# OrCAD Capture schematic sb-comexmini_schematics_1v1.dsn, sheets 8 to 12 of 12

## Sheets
8 POWER: size Custom; title: POWER; note: 8005536002
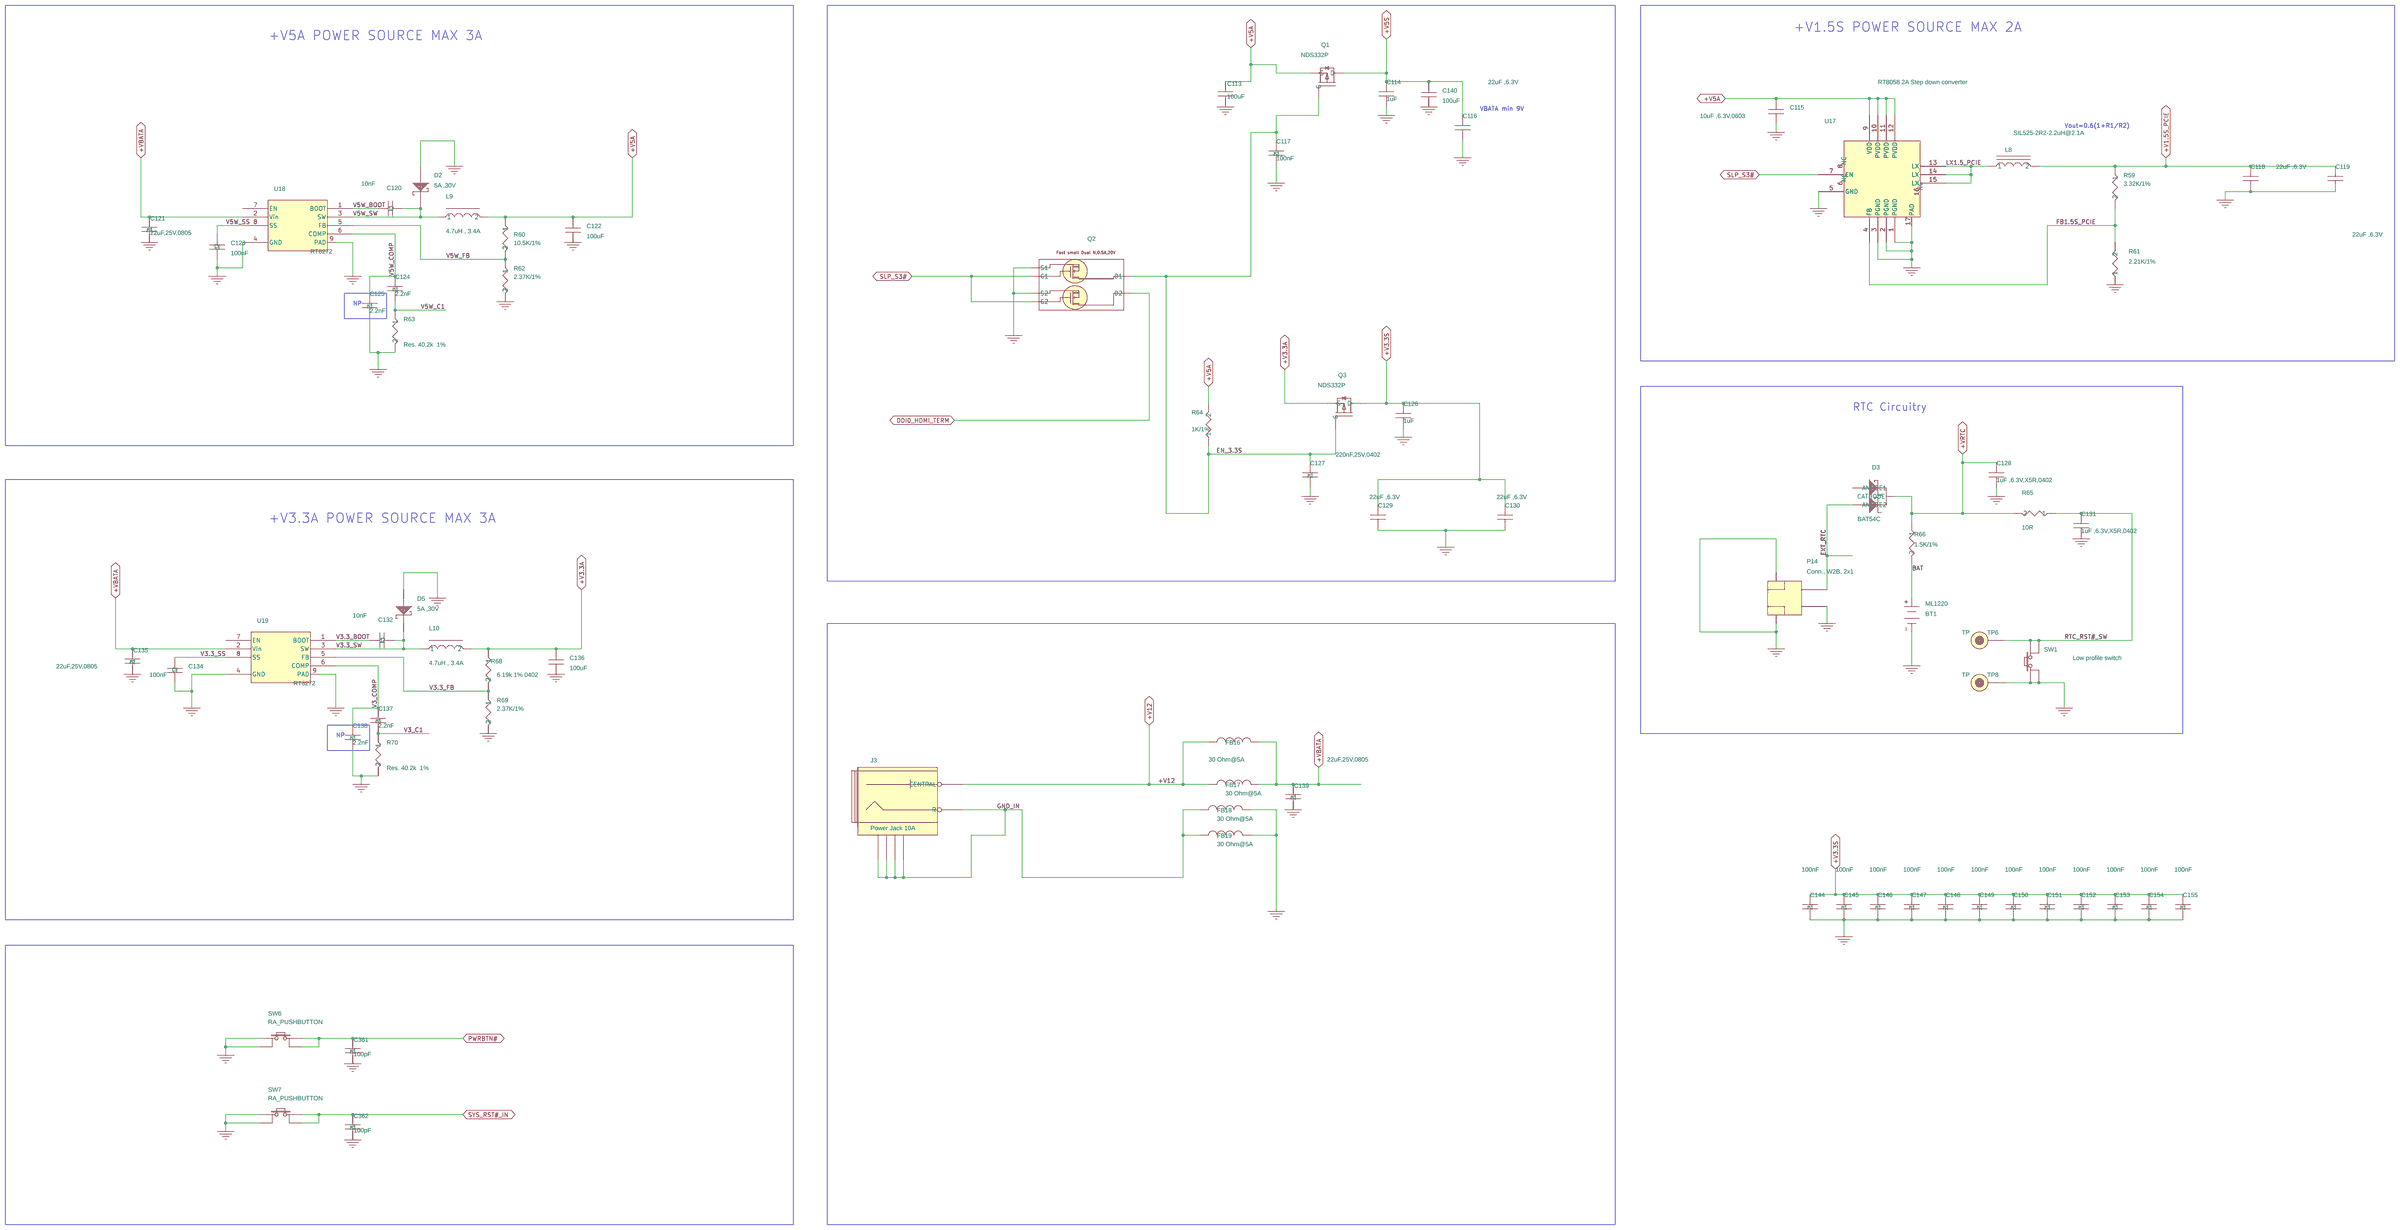
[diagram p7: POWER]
9 SPI BIOS & EC: size Custom; title: DEBUG; note: 8001015000
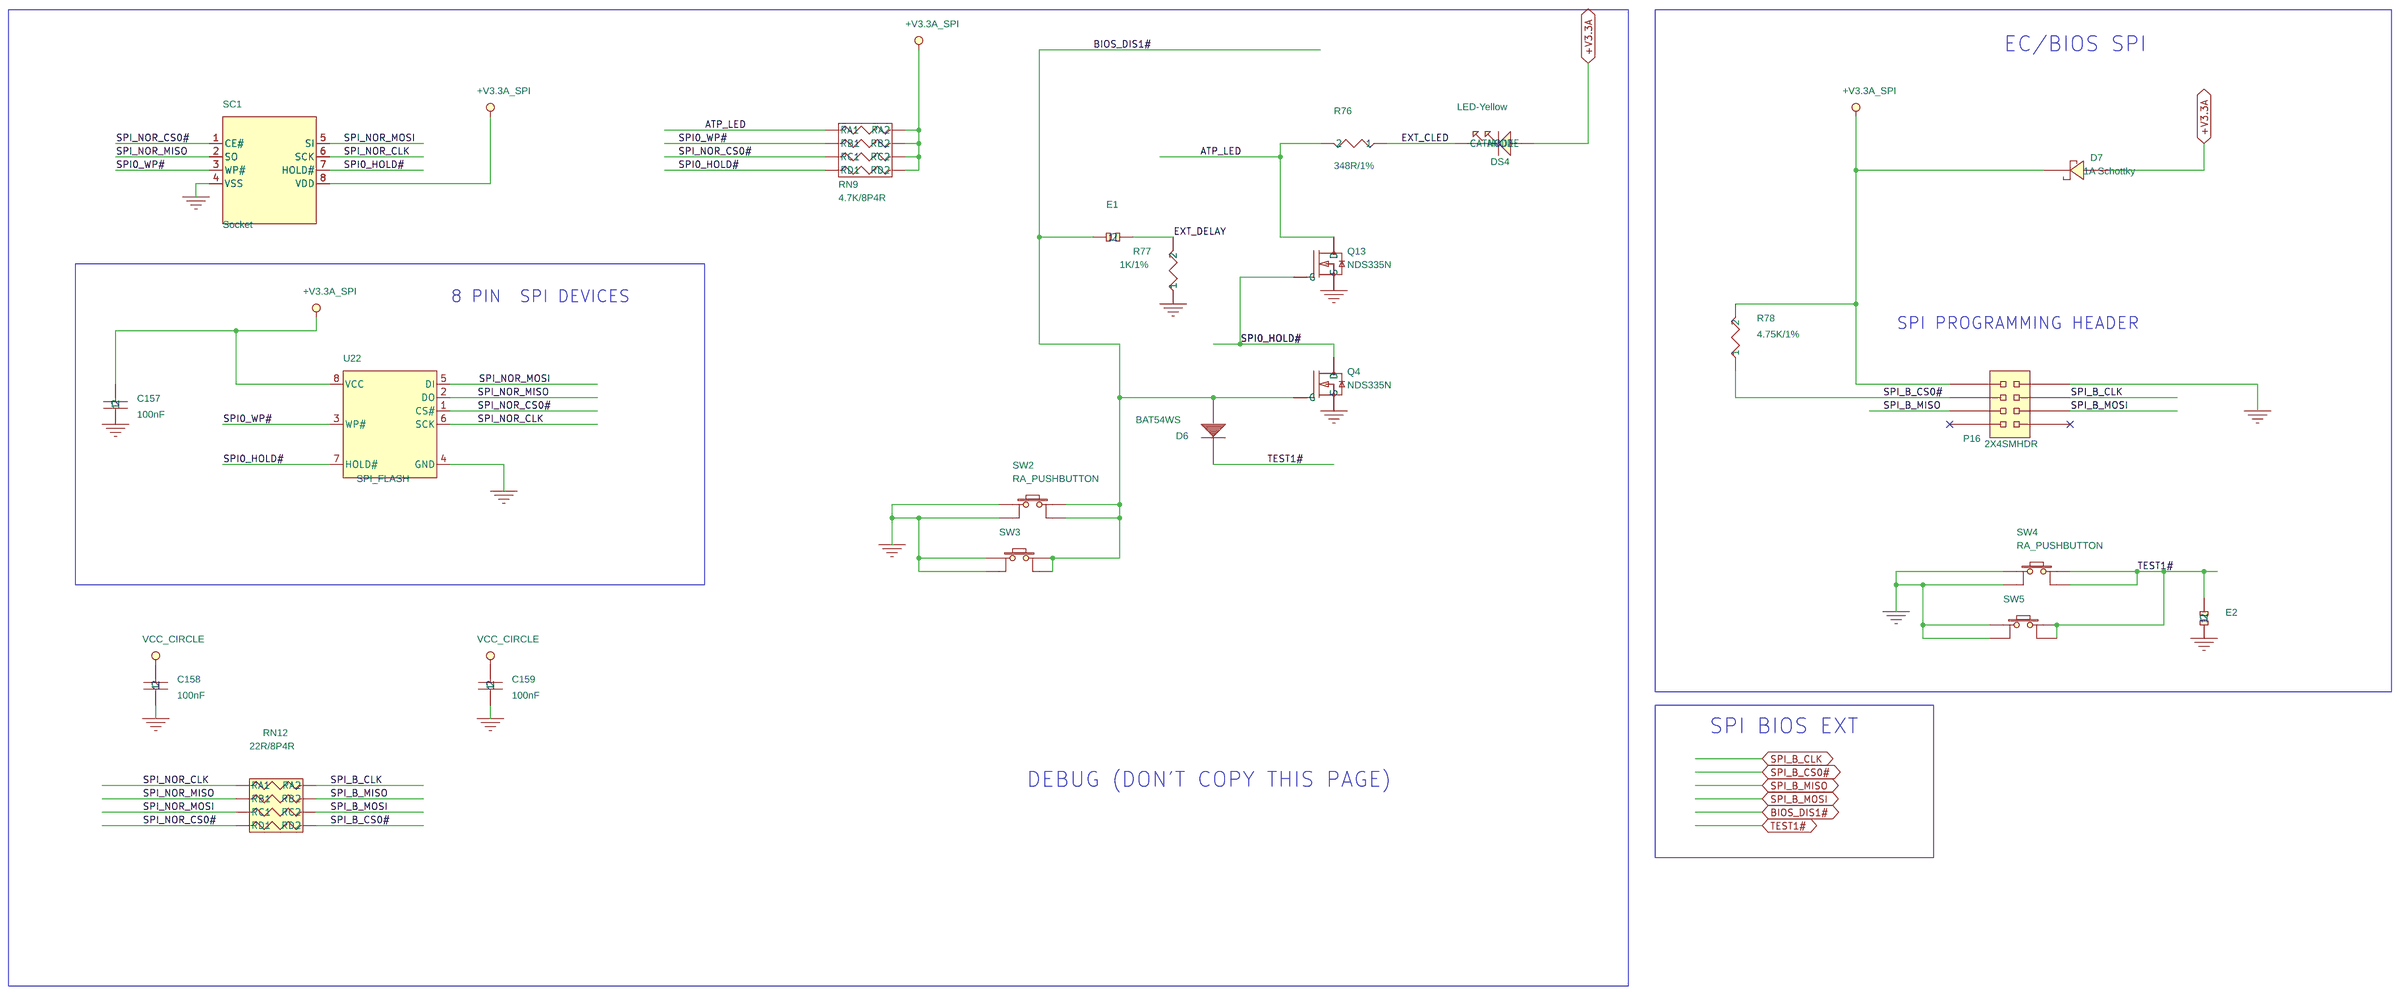
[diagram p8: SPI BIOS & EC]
10 PORT80: size Custom; title: PORT 80; note: 8001015000
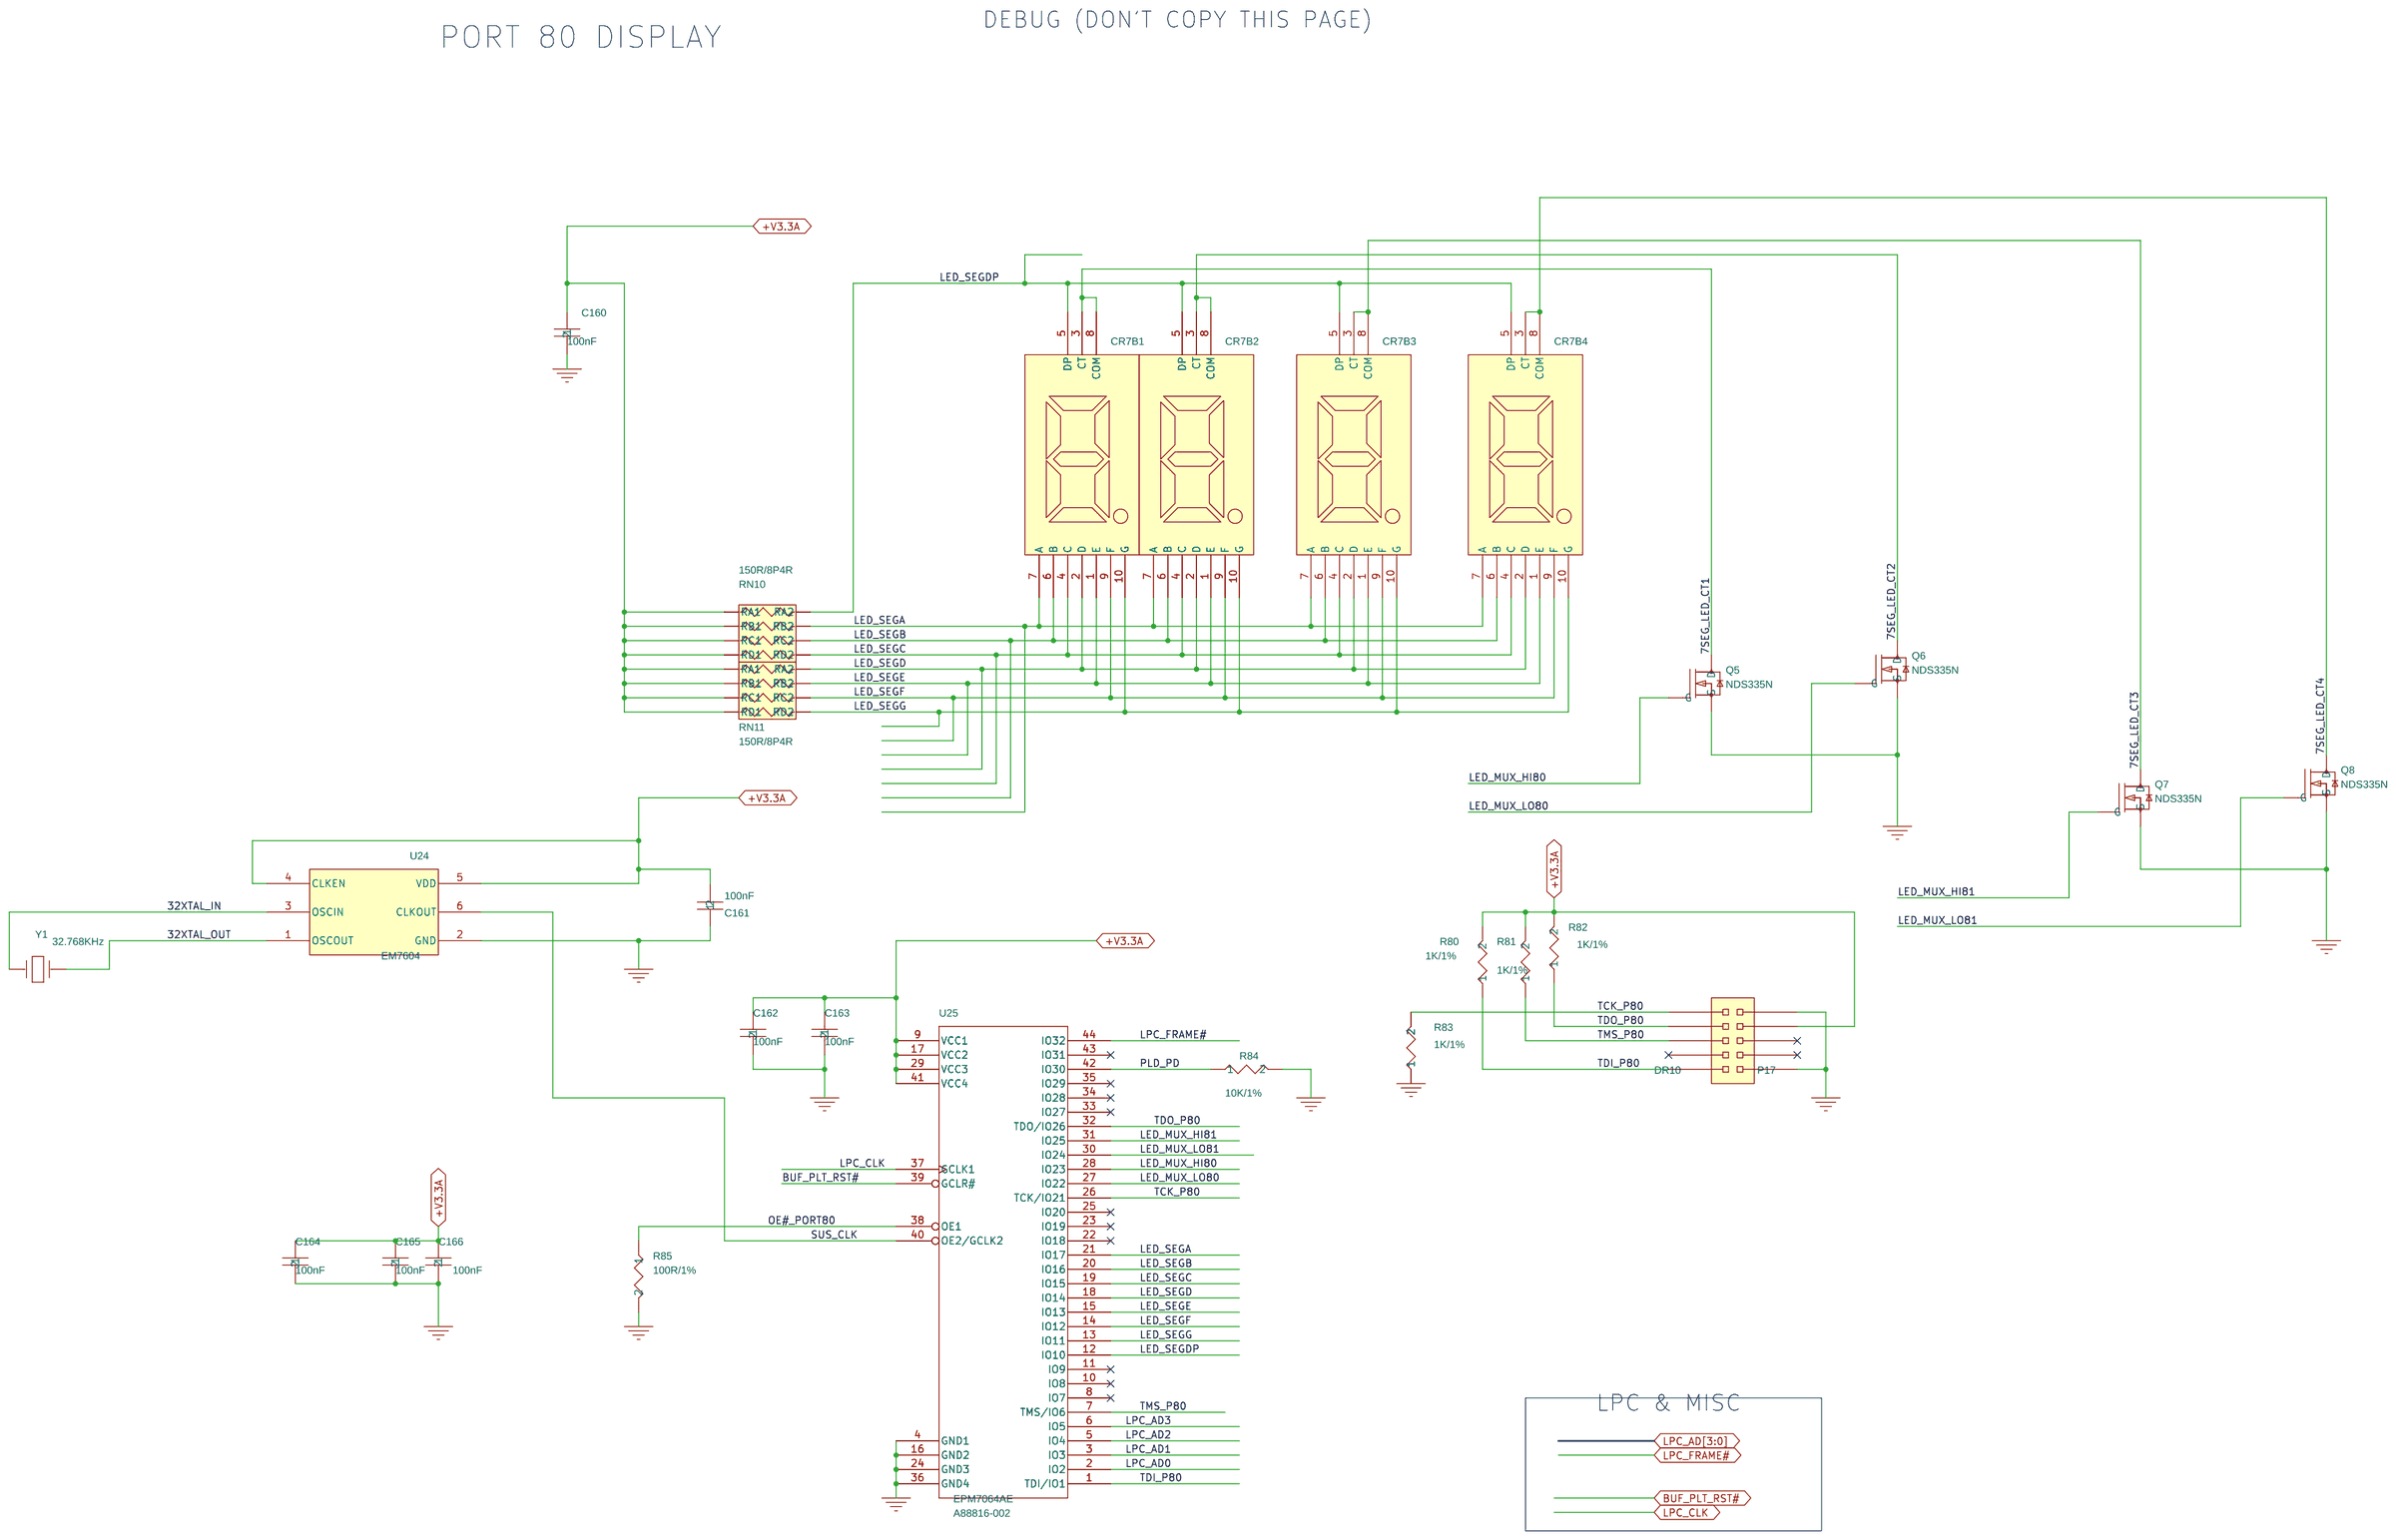
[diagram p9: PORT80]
11 HDMI PORT(DDI0): size Custom; title: HDMI DDI0
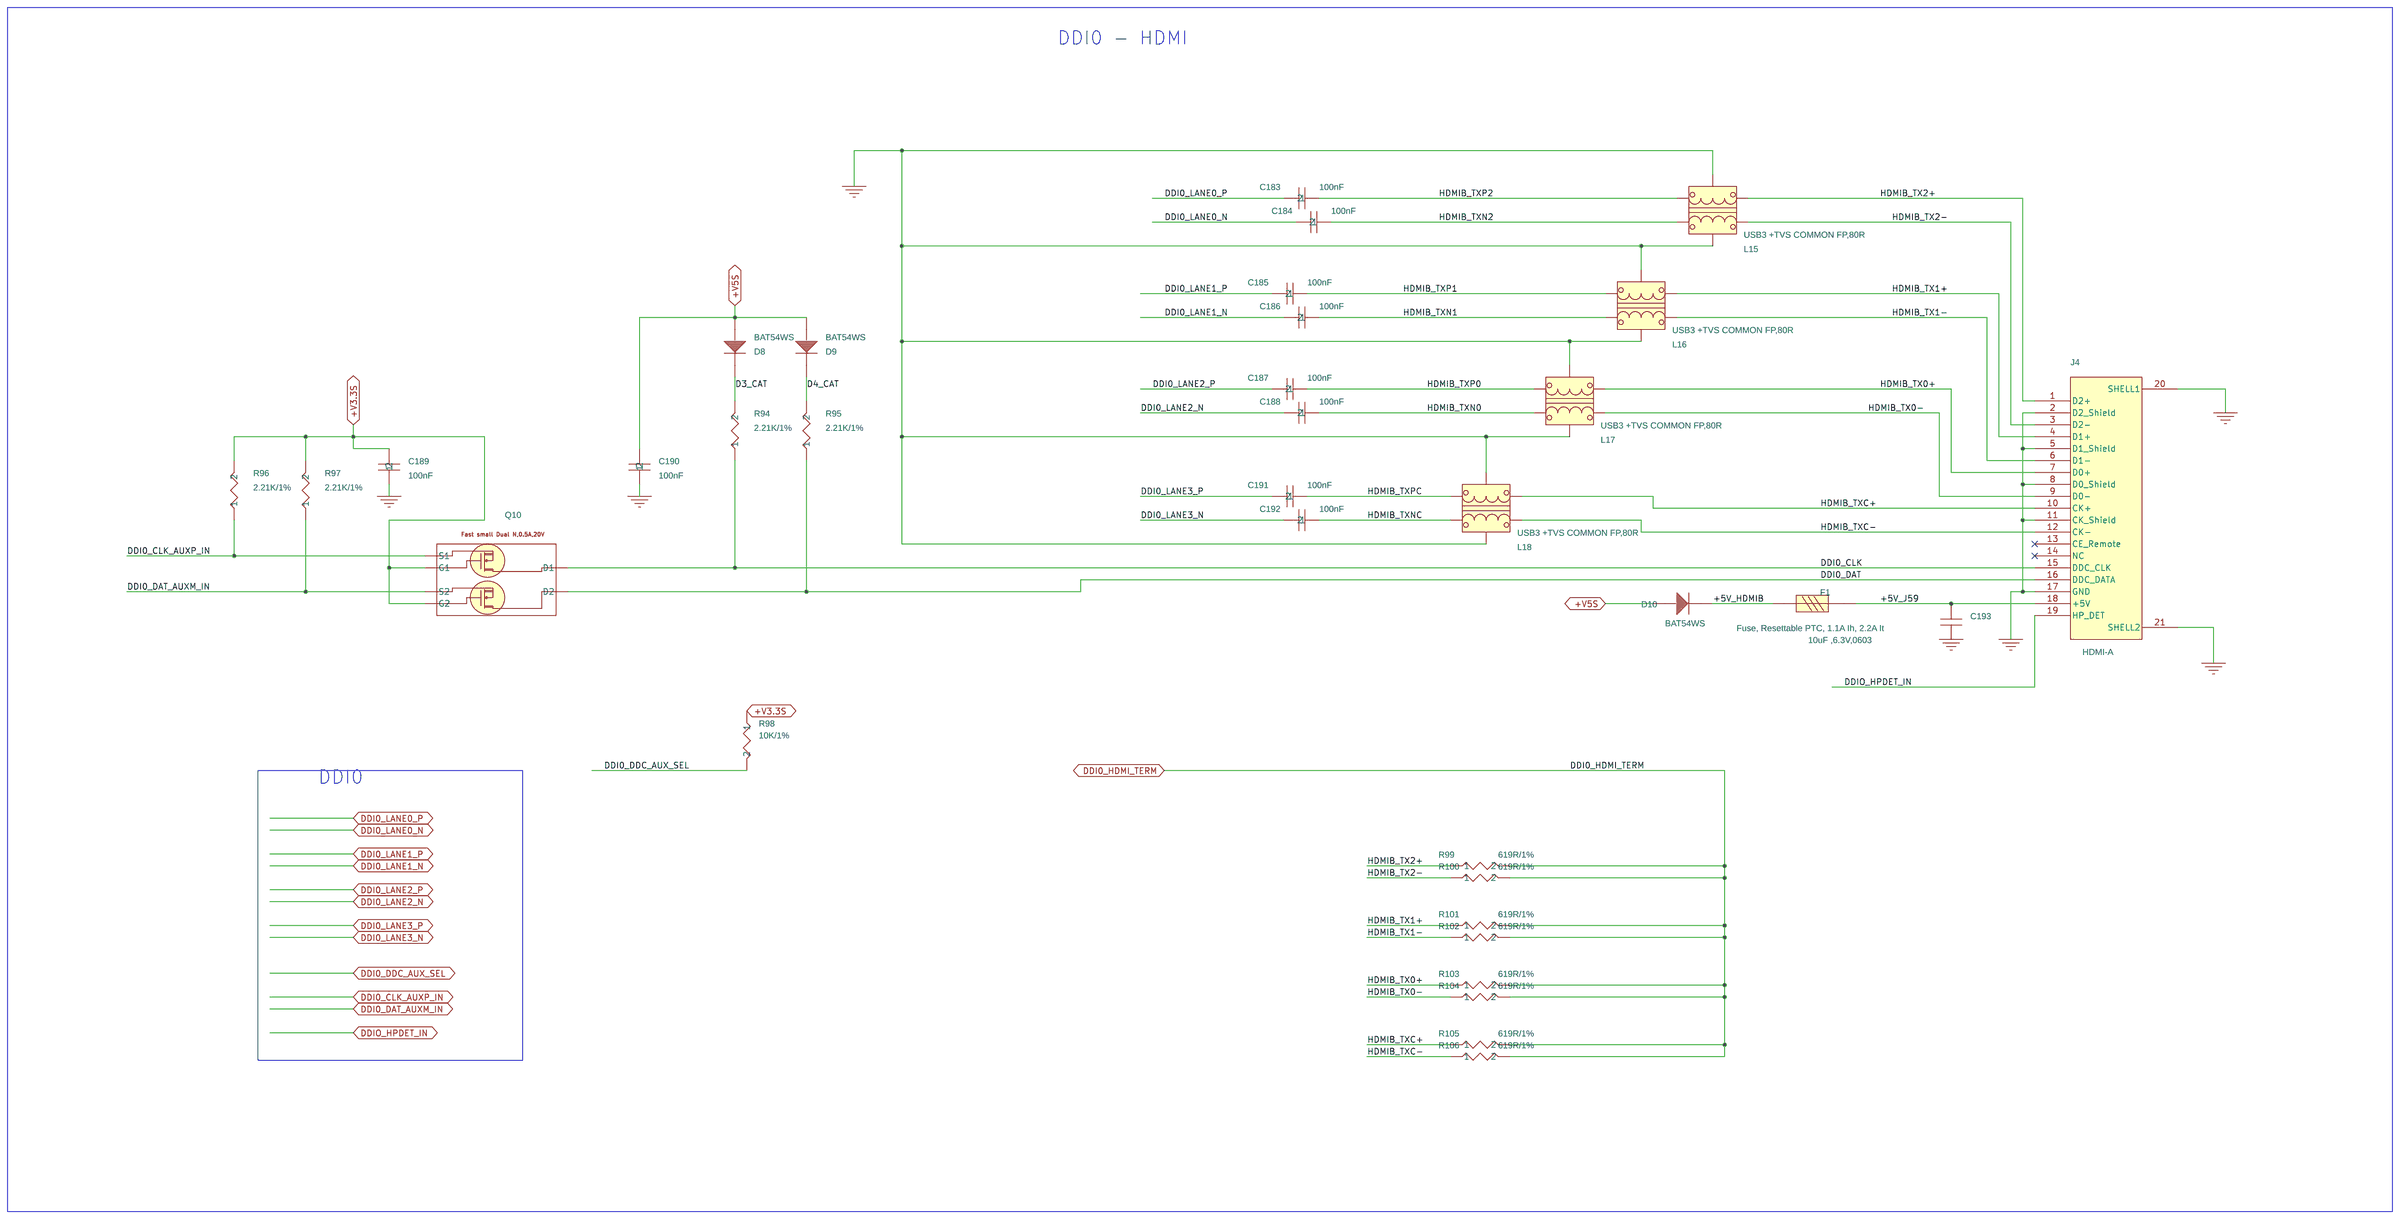
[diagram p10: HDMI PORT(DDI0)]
12 DISPLAY PORT (DDI1): size Custom; title: Display Port / LVDS
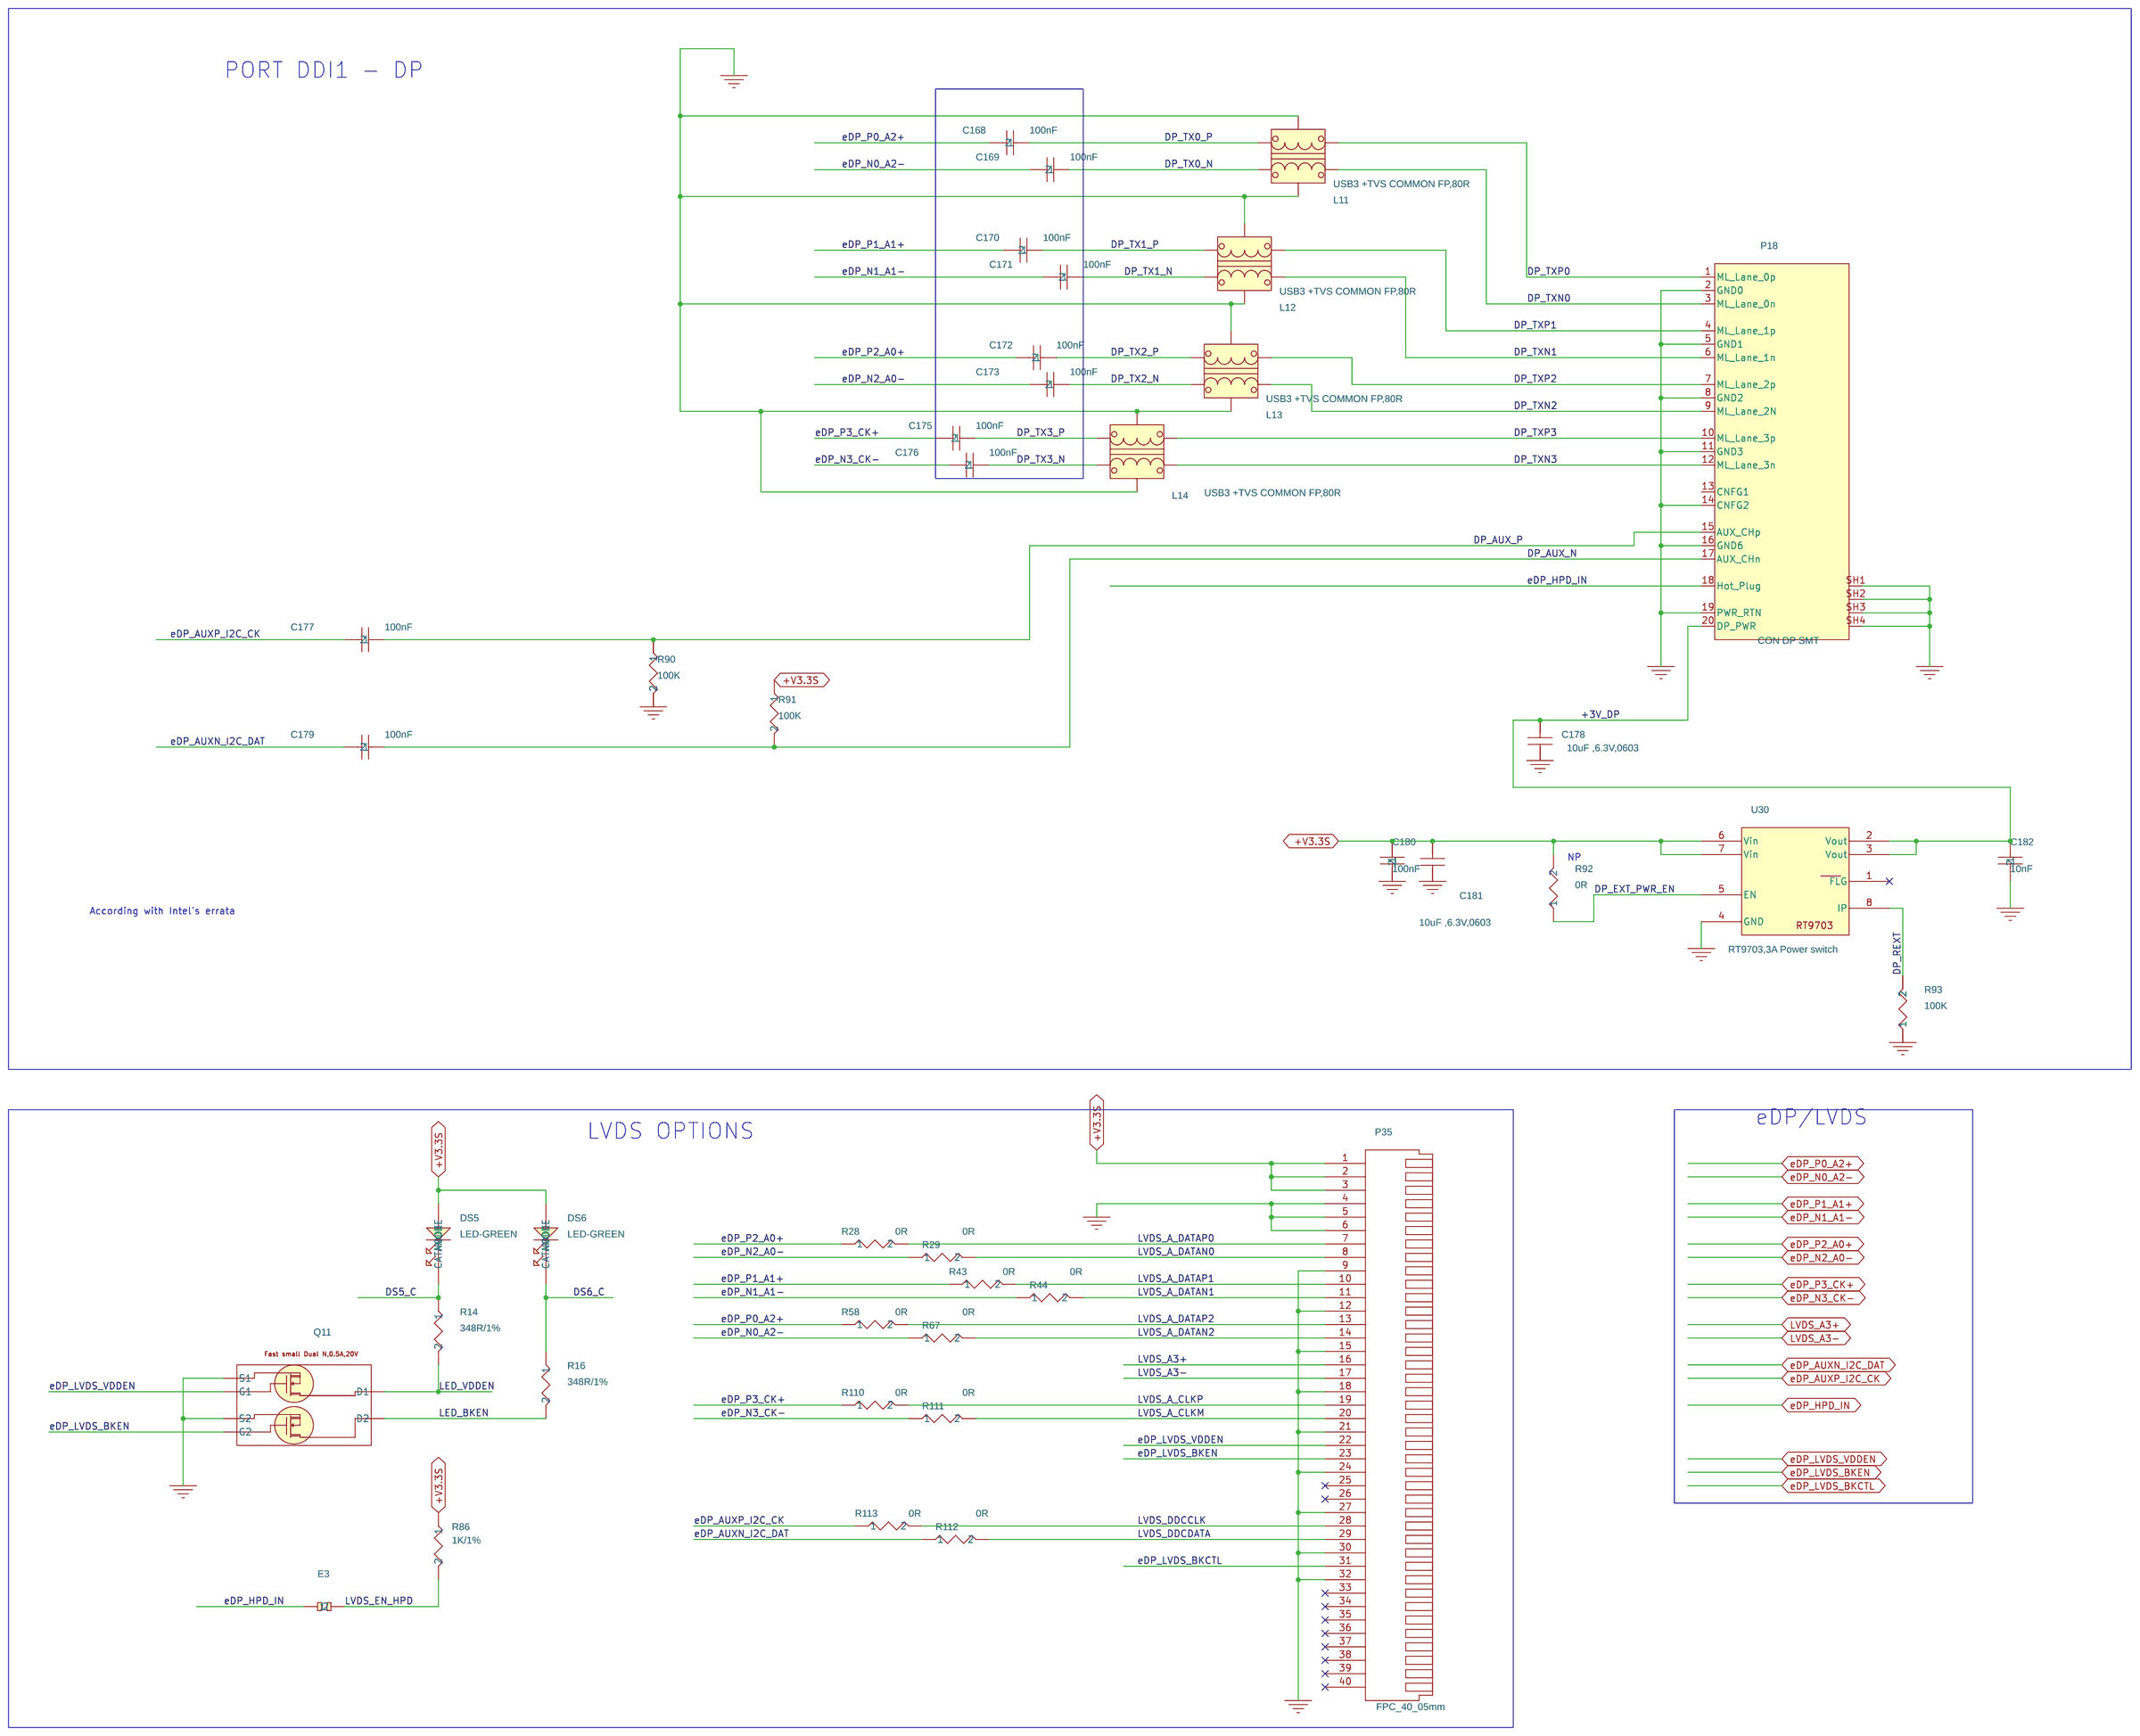
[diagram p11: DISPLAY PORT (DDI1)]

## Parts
sheet DISPLAY PORT (DDI1)
C168  100nF  [RC0402]
C169  100nF  [RC0402]
C170  100nF  [RC0402]
C171  100nF  [RC0402]
C172  100nF  [RC0402]
C173  100nF  [RC0402]
C175  100nF  [RC0402]
C176  100nF  [RC0402]
C177  100nF  [RC0402]
C178  10uF ,6.3V,0603  [RC0603]
C179  100nF  [RC0402]
C180  100nF  [RC0402]
C181  10uF ,6.3V,0603  [RC0603]
C182  10nF  [RC0402]
DS5  LED-GREEN  [LED-1206]
DS6  LED-GREEN  [LED-1206]
E3  HDR1X2  [1X2THHDR]
L11  USB3 +TVS COMMON FP,80R  [EMI1012-ESD]
L12  USB3 +TVS COMMON FP,80R  [EMI1012-ESD]
L13  USB3 +TVS COMMON FP,80R  [EMI1012-ESD]
L14  USB3 +TVS COMMON FP,80R  [EMI1012-ESD]
P18  CON DP SMT  [DP-F-RA-SM]
P35  FPC_40_05mm  [FPC05SM40-1]
Q11  MOSFET,DUAL-N,0.4A@20V  [SOT-563-6]
R14  348R/1%  [RC0402]
R16  348R/1%  [RC0402]
R28  0R  [RC0402]
R29  0R  [RC0402]
R43  0R  [RC0402]
R44  0R  [RC0402]
R58  0R  [RC0402]
R67  0R  [RC0402]
R86  1K/1%  [RC0402]
R90  100K  [RC0402]
R91  100K  [RC0402]
R92  0R  [RC0402]
R93  100K  [RC0402]
R110  0R  [RC0402]
R111  0R  [RC0402]
R112  0R  [RC0402]
R113  0R  [RC0402]
U30  RT9703,3A Power switch  [SO-8-150]
sheet HDMI PORT(DDI0)
C183  100nF  [RC0402]
C184  100nF  [RC0402]
C185  100nF  [RC0402]
C186  100nF  [RC0402]
C187  100nF  [RC0402]
C188  100nF  [RC0402]
C189  100nF  [RC0402]
C190  100nF  [RC0402]
C191  100nF  [RC0402]
C192  100nF  [RC0402]
C193  10uF ,6.3V,0603  [RC0603]
D8  BAT54WS  [SOD-323]
D9  BAT54WS  [SOD-323]
D10  BAT54WS  [SOD-323]
F1  Fuse, Resettable PTC, 1.1A Ih, 2.2A It  [FUSE-1206]
J4  HDMI-A  [SMT(HDMI-A)]
L15  USB3 +TVS COMMON FP,80R  [EMI1012-ESD]
L16  USB3 +TVS COMMON FP,80R  [EMI1012-ESD]
L17  USB3 +TVS COMMON FP,80R  [EMI1012-ESD]
L18  USB3 +TVS COMMON FP,80R  [EMI1012-ESD]
Q10  MOSFET,DUAL-N,0.4A@20V  [SOT-563-6]
R94  2.21K/1%
R95  2.21K/1%
R96  2.21K/1%
R97  2.21K/1%
R98  10K/1%  [RC0402]
R99  619R/1%
R100  619R/1%
R101  619R/1%
R102  619R/1%
R103  619R/1%
R104  619R/1%
R105  619R/1%
R106  619R/1%
sheet PORT80
C160  100nF  [RC0402]
C161  100nF  [RC0402]
C162  100nF  [RC0402]
C163  100nF  [RC0402]
C164  100nF  [RC0402]
C165  100nF  [RC0402]
C166  100nF  [RC0402]
CR7B1  IC,SMT,7SegDisp,CC  [APSC02-41-CN22]
CR7B2  IC,SMT,7SegDisp,CC  [APSC02-41-CN22]
CR7B3  IC,SMT,7SegDisp,CC  [APSC02-41-CN22]
CR7B4  IC,SMT,7SegDisp,CC  [APSC02-41-CN22]
P17  DR10  [2X5THHDR]
Q5  NDS335N  [SOT23]
Q6  NDS335N  [SOT23]
Q7  NDS335N  [SOT23]
Q8  NDS335N  [SOT23]
R80  1K/1%  [RC0402]
R81  1K/1%  [RC0402]
R82  1K/1%  [RC0402]
R83  1K/1%  [RC0402]
R84  10K/1%  [RC0402]
R85  100R/1%  [RC0402]
RN10  150R/8P4R  [RESNET8P1206]
RN11  150R/8P4R  [RESNET8P1206]
U24  EM7604  [SOT23-6L]
U25  EPM7064AE  [PQFP44_8MM]
Y1  32.768KHz  [XTAL3_2x1_5]
sheet POWER
BT1  ML1220  [BT1220SM]
C113  100uF  [C1210H2_5]
C114  1uF  [RC0402]
C115  10uF ,6.3V,0603  [RC0603]
C116  22uF ,6.3V  [0805]
C117  100nF  [RC0402]
C118  22uF ,6.3V  [0805]
C119  22uF ,6.3V  [0805]
C120  10nF  [RC0402]
C121  22uF,25V,0805  [RC0805]
C122  100uF  [C1210H2_5]
C123  100nF  [RC0402]
C124  2.2nF  [RC0402]
C125  2.2nF  [RC0402]
C126  1uF  [RC0402]
C127  220nF,25V,0402  [RC0402]
C128  1uF ,6.3V,X5R,0402  [RC0402]
C129  22uF ,6.3V  [0805]
C130  22uF ,6.3V  [0805]
C131  1uF ,6.3V,X5R,0402  [RC0402]
C132  10nF  [RC0402]
C134  100nF  [RC0402]
C135  22uF,25V,0805  [RC0805]
C136  100uF  [C1210H2_5]
C137  2.2nF  [RC0402]
C138  2.2nF  [RC0402]
C139  22uF,25V,0805  [RC0805]
C140  100uF  [C1210H2_5]
C144  100nF  [RC0402]
C145  100nF  [RC0402]
C146  100nF  [RC0402]
C147  100nF  [RC0402]
C148  100nF  [RC0402]
C149  100nF  [RC0402]
C150  100nF  [RC0402]
C151  100nF  [RC0402]
C152  100nF  [RC0402]
C153  100nF  [RC0402]
C154  100nF  [RC0402]
C155  100nF  [RC0402]
C361  100pF  [RC0402]
C362  100pF  [RC0402]
D2  5A ,30V  [SOD-128]
D3  BAT54C  [SOT23]
D5  5A ,30V  [SOD-128]
FB16  30 Ohm@5A  [FB0603]
FB17  30 Ohm@5A  [FB0603]
FB18  30 Ohm@5A  [FB0603]
FB19  30 Ohm@5A  [FB0603]
J3  Power Jack 10A  [PJ-0810-TH]
L8  SIL525-2R2-2.2uH@2.1A
L9  4.7uH , 3.4A  [IND7_3x7_3SM]
L10  4.7uH , 3.4A  [IND7_3x7_3SM]
P14  Conn., W2B, 2x1  [1x2W2B1_25RASM]
Q1  NDS332P  [SOT23]
Q2  MOSFET,DUAL-N,0.4A@20V  [SOT-563-6]
Q3  NDS332P  [SOT23]
R59  3.32K/1%  [RC0402]
R60  10.5K/1%  [RC0402]
R61  2.21K/1%
R62  2.37K/1%  [RC0402]
R63  Res. 40.2k  1%  [0402]
R64  1K/1%  [RC0402]
R65  10R  [RC0402]
R66  1.5K/1%  [RC0402]
R68  6.19k 1% 0402  [RC0402]
R69  2.37K/1%  [RC0402]
R70  Res. 40.2k  1%  [0402]
SW1  Low profile switch  [TACSW4x6SMRA]
SW6  RA_PUSHBUTTON  [TACSW4x6SMRA]
SW7  RA_PUSHBUTTON  [TACSW4x6SMRA]
TP6  TP
TP8  TP
U17  RT8058 2A Step down converter  [WQFN-16L3x3]
U18  RT8272  [PSOP-8-2X2]
U19  RT8272  [PSOP-8-2X2]
sheet SPI BIOS & EC
C157  100nF  [RC0402]
C158  100nF  [RC0402]
C159  100nF  [RC0402]
D6  BAT54WS  [SOD-323]
D7  1A Schottky  [SOD-123]
DS4  LED-Yellow  [LED-1206]
E1  HDR1X2  [1X2THHDR]
E2  HDR1X2  [1X2THHDR]
P16  2X4SMHDR  [2X4SMHDR]
Q4  NDS335N  [SOT23]
Q13  NDS335N  [SOT23]
R76  348R/1%  [RC0402]
R77  1K/1%  [RC0402]
R78  4.75K/1%  [RC0402]
RN9  4.7K/8P4R  [RESNET8P0805]
RN12  22R/8P4R  [RESNET8P0805]
SC1  Socket  [SOIC 200mil]
SW2  RA_PUSHBUTTON  [TACSW4x6SMRA]
SW3  PushB  [TACTSW6x6SM]
SW4  RA_PUSHBUTTON  [TACSW4x6SMRA]
SW5  PushB  [TACTSW6x6SM]
U22  SPI_FLASH  [soi8_208mil_85h]

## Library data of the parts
C168 = 100nF,_10V,_X7R,_10%,_0402_4: CLABCONF0: =SB-COMEXmini AND NOT L
C169 = 100nF,_10V,_X7R,_10%,_0402_2: CLABCONF0: =SB-COMEXmini AND NOT L
C170 = 100nF,_10V,_X7R,_10%,_0402_5: CLABCONF0: =SB-COMEXmini AND NOT L
C171 = 100nF,_10V,_X7R,_10%,_0402_7: CLABCONF0: =SB-COMEXmini AND NOT L
C172 = 100nF,_10V,_X7R,_10%,_0402_10: CLABCONF0: =SB-COMEXmini AND NOT L
C173 = 100nF,_10V,_X7R,_10%,_0402: CLABCONF0: =SB-COMEXmini AND NOT L
C175 = 100nF,_10V,_X7R,_10%,_0402_3: CLABCONF0: =SB-COMEXmini AND NOT L
C176 = 100nF,_10V,_X7R,_10%,_0402_8: CLABCONF0: =SB-COMEXmini AND NOT L
C177 = 100nF,_10V,_X7R,_10%,_0402_1: CLABCONF0: =SB-COMEXmini AND NOT L
C178 = Cap.,10uF,6.3V,0603,X5R_1: CLABCONF0: =SB-COMEXmini AND NOT L
C179 = 100nF,_10V,_X7R,_10%,_0402_9: CLABCONF0: =SB-COMEXmini AND NOT L
C180 = 100nF,_10V,_X7R,_10%,_0402_6: CLABCONF0: =SB-COMEXmini; Group: Front Panel
C115 C181 C193 = Cap.,10uF,6.3V,0603,X5R: CLABCONF0: =SB-COMEXmini
C182 = 10nF,_25V,_X7R,_10%,_0402: CLABCONF0: =SB-COMEXmini AND NOT L
DS5 = LED-GREEN_1206_1: CLABCONF0: =L; Group: Always
DS6 = LED-GREEN_1206: CLABCONF0: =L; Group: Always
E3 = HDR_1x2_100MIL_TH_JUMPER: CLABCONF0: =L
L11-L14 = EMI,_USB3_CHOKE: CLABCONF0: 142D11801S=SB-COMEXmini AND NOT L
P18 = Conn,DP,SMT,RA: CLABCONF0: =SB-COMEXmini AND NOT L
P35 = FPC_40_05mm: CLABCONF0: =L
Q11 = MOSFET,DUAL-N,0.4A@20V: CLABCONF0: =L
R14 = 348R,1%,0402,1_16W: CLABCONF0: =L
R16 = 348R,1%,0402,1_16W_1: CLABCONF0: =L
R28 = 0R,_0402_8: CLABCONF0: =L
R29 = 0R,_0402_4: CLABCONF0: =L
R43 = 0R,_0402: CLABCONF0: =L
R44 = 0R,_0402_5: CLABCONF0: =L
R58 = 0R,_0402_6: CLABCONF0: =L
R67 = 0R,_0402_1: CLABCONF0: =L
R64 R77 R86 = 1K,1%,0402,1_16W: CLABCONF0: =SB-COMEXmini
R90 = 100K,_0402_2: CLABCONF0: =SB-COMEXmini AND NOT L
R91 = 100K,_0402_1: CLABCONF0: =SB-COMEXmini AND NOT L
R92 = 0R,_0402_7: CLABCONF0: =SB-COMEXmini AND NOT L
R93 = 100K,_0402: CLABCONF0: =SB-COMEXmini AND NOT L
R110 = 0R,_0402_9: CLABCONF0: =L
R111 = 0R,_0402_2: CLABCONF0: =L
R112 = 0R,_0402_3: CLABCONF0: =L
R113 = 0R,_0402_10: CLABCONF0: =L
U30 = RT9703,3A_Power_switch+FLG: CLABCONF0: =SB-COMEXmini AND NOT L
C117 C183 = 100nF,_10V,_X7R,_10%,_0402_6: CLABCONF0: =SB-COMEXmini
C157 C184 = 100nF,_10V,_X7R,_10%,_0402_2: CLABCONF0: =SB-COMEXmini
C158 C185 = 100nF,_10V,_X7R,_10%,_0402_1: CLABCONF0: =SB-COMEXmini
C186 = 100nF,_10V,_X7R,_10%,_0402_7: CLABCONF0: =SB-COMEXmini
C187 = 100nF,_10V,_X7R,_10%,_0402_5: CLABCONF0: =SB-COMEXmini
C188 = 100nF,_10V,_X7R,_10%,_0402_9: CLABCONF0: =SB-COMEXmini
C159 C189 = 100nF,_10V,_X7R,_10%,_0402: CLABCONF0: =SB-COMEXmini
C190 = 100nF,_10V,_X7R,_10%,_0402_8: CLABCONF0: =SB-COMEXmini
C134 C191 = 100nF,_10V,_X7R,_10%,_0402_4: CLABCONF0: =SB-COMEXmini
C192 = 100nF,_10V,_X7R,_10%,_0402_3: CLABCONF0: =SB-COMEXmini
D8-D10 = BAT54WS_0: CLABCONF0: =SB-COMEXmini
F1 = Fuse,_1.1_A_Ih,_2.2A_It: CLABCONF0: =SB-COMEXmini
J4 = HDMI_Connector: CLABCONF0: =SB-COMEXmini; MFG-P/N: JAE - DC1R019JD1; MFG/SUPL: JAE - DC1R019JD1
L15-L18 = EMI,_USB3_CHOKE: CLABCONF0: 142D11801S=SB-COMEXmini
Q2 Q10 = MOSFET,DUAL-N,0.4A@20V: CLABCONF0: =SB-COMEXmini
R94 = 2.21k_1%_0402_3: CLABCONF0: =SB-COMEXmini
R95 = 2.21k_1%_0402_1: CLABCONF0: =SB-COMEXmini
R96 = 2.21k_1%_0402_2: CLABCONF0: =SB-COMEXmini
R61 R97 = 2.21k_1%_0402: CLABCONF0: =SB-COMEXmini
R98 = 10K,1%,0402,1_16W: CLABCONF0: =SB-COMEXmini
R99 = 619R,1%,0402,1_16W_1: CLABCONF0: =SB-COMEXmini
R100 = 619R,1%,0402,1_16W_5: CLABCONF0: =SB-COMEXmini
R101 = 619R,1%,0402,1_16W_2: CLABCONF0: =SB-COMEXmini
R102 = 619R,1%,0402,1_16W: CLABCONF0: =SB-COMEXmini
R103 = 619R,1%,0402,1_16W_3: CLABCONF0: =SB-COMEXmini
R104 = 619R,1%,0402,1_16W_6: CLABCONF0: =SB-COMEXmini
R105 = 619R,1%,0402,1_16W_4: CLABCONF0: =SB-COMEXmini
R106 = 619R,1%,0402,1_16W_7: CLABCONF0: =SB-COMEXmini
C160 = 100nF,_10V,_X7R,_10%,_0402_3: CLABCONF0: =DEBUG; CLABCONF1: =SB-COMEXmini
C161 = 100nF,_10V,_X7R,_10%,_0402_1: CLABCONF0: =DEBUG; CLABCONF1: =SB-COMEXmini
C162 = 100nF,_10V,_X7R,_10%,_0402_2: CLABCONF0: =DEBUG; CLABCONF1: =SB-COMEXmini
C163 = 100nF,_10V,_X7R,_10%,_0402_4: CLABCONF0: =DEBUG; CLABCONF1: =SB-COMEXmini
C164 = 100nF,_10V,_X7R,_10%,_0402_6: CLABCONF0: =DEBUG; CLABCONF1: =SB-COMEXmini
C165 = 100nF,_10V,_X7R,_10%,_0402_5: $LOCATION: =NOP; CLABCONF0: =DEBUG; CLABCONF1: =SB-COMEXmini
C166 = 100nF,_10V,_X7R,_10%,_0402: CLABCONF0: =DEBUG; CLABCONF1: =SB-COMEXmini
CR7B1-CR7B4 = IC,SMT,7SegDisp,CC: CLABCONF0: =DEBUG; CLABCONF1: =SB-COMEXmini
P17 = HDR_2x5_100MIL_TH: CLABCONF0: =DEBUG; CLABCONF1: =SB-COMEXmini
Q5-Q8 = N-MOSFET,NDS335N,100mOhm@2.5V: CLABCONF0: =DEBUG; CLABCONF1: =SB-COMEXmini
R80 = 1K,1%,0402,1_16W_3: CLABCONF0: =DEBUG; CLABCONF1: =SB-COMEXmini
R81 = 1K,1%,0402,1_16W_2: CLABCONF0: =DEBUG; CLABCONF1: =SB-COMEXmini
R82 = 1K,1%,0402,1_16W_1: CLABCONF0: =DEBUG; CLABCONF1: =SB-COMEXmini
R83 = 1K,1%,0402,1_16W: CLABCONF0: =DEBUG; CLABCONF1: =SB-COMEXmini
R84 = 10K,1%,0402,1_16W: CLABCONF0: =DEBUG; CLABCONF1: =SB-COMEXmini
R85 = 100R,1%,0402,1_16W: CLABCONF0: =DEBUG; CLABCONF1: =SB-COMEXmini
RN10 RN11 = RN,150R,8P4R@1206: CLABCONF0: =DEBUG; CLABCONF1: =SB-COMEXmini
U24 = OSC.,_26.000MHz,100PPM,_1_1.8V: CLABCONF0: =DEBUG; CLABCONF1: =SB-COMEXmini; P/N: 105I76040S
U25 = IC,PLD,BLANK,EPM7064AE,TQFP44: CLABCONF0: =DEBUG; CLABCONF1: =SB-COMEXmini; DEVICE: A88816-002; FINANCE: DEBUG_PORT80; IPN: A88816-002; P/N: 107A66470S; PART_NUMBER: A88816-002
Y1 = XTAL,_32.768KHZ,_20PPM,_4x1.5mm: CLABCONF0: =DEBUG; CLABCONF1: =SB-COMEXmini; P/N: 141B32301I
BT1 = ML1020: CLABCONF0: =SB-COMEXmini
C113 = 100uF,_6.3V,_X5R,_20%,_1206: CLABCONF0: =SB-COMEXmini
C114 C126 = 1uF,X5R,6.3V,0402: CLABCONF0: =SB-COMEXmini
C116 = Cap.,22uF,6.3V,X5R_2: CLABCONF0: =SB-COMEXmini
C118 = Cap.,22uF,6.3V,X5R_1: CLABCONF0: =SB-COMEXmini
C119 = Cap.,22uF,6.3V,X5R_3: CLABCONF0: =SB-COMEXmini
C120 = 10nF,_25V,_X7R,_10%,_0402_1: CLABCONF0: =SB-COMEXmini
C121 = 22uF,_25V,_X7R_X5R,_20%,_0805: CLABCONF0: =SB-COMEXmini
C122 C136 C140 = 100uF,_6.3V,_X5R,_20%,_1206: CLABCONF0: =SB-COMEXmini; Group: Always
C123 = 100nF,_10V,_X7R,_10%,_0402_12: CLABCONF0: =SB-COMEXmini
C124 = 2.2nF,_50V,_X7R,_10%,_0402_1: CLABCONF0: =SB-COMEXmini
C125 = 2.2nF,_50V,_X7R,_10%,_0402_3: CLABCONF0: =NOP
C127 = 220nF,_25V,_X7R,_10%,_0402: CLABCONF0: =SB-COMEXmini
C128 C131 = Cap_1uF,X5R,6.3V,0402: CLABCONF0: =SB-COMEXmini
C129 = Cap.,22uF,6.3V,X5R: CLABCONF0: =SB-COMEXmini
C130 = Cap.,22uF,6.3V,X5R_4: CLABCONF0: =SB-COMEXmini
C132 = 10nF,_25V,_X7R,_10%,_0402: CLABCONF0: =SB-COMEXmini
C135 = 22uF,_25V,_X7R_X5R,_20%,_0805_2: CLABCONF0: =SB-COMEXmini
C137 = 2.2nF,_50V,_X7R,_10%,_0402: CLABCONF0: =SB-COMEXmini
C138 = 2.2nF,_50V,_X7R,_10%,_0402_2: CLABCONF0: =NOP
C139 = 22uF,_25V,_X7R_X5R,_20%,_0805_1: CLABCONF0: =SB-COMEXmini
C144 = 100nF,_10V,_X7R,_10%,_0402_1: CLABCONF0: =SB-COMEXmini; Group: NPOP
C145 = 100nF,_10V,_X7R,_10%,_0402_2: CLABCONF0: =SB-COMEXmini; Group: NPOP
C146 = 100nF,_10V,_X7R,_10%,_0402_3: CLABCONF0: =SB-COMEXmini; Group: NPOP
C147 = 100nF,_10V,_X7R,_10%,_0402_5: CLABCONF0: =SB-COMEXmini; Group: NPOP
C148 = 100nF,_10V,_X7R,_10%,_0402_8: CLABCONF0: =SB-COMEXmini; Group: NPOP
C149 = 100nF,_10V,_X7R,_10%,_0402_7: CLABCONF0: =SB-COMEXmini; Group: NPOP
C150 = 100nF,_10V,_X7R,_10%,_0402_10: CLABCONF0: =SB-COMEXmini; Group: NPOP
C151 = 100nF,_10V,_X7R,_10%,_0402_13: CLABCONF0: =SB-COMEXmini; Group: NPOP
C152 = 100nF,_10V,_X7R,_10%,_0402_11: CLABCONF0: =SB-COMEXmini; Group: NPOP
C153 = 100nF,_10V,_X7R,_10%,_0402_9: CLABCONF0: =SB-COMEXmini; Group: NPOP
C154 = 100nF,_10V,_X7R,_10%,_0402_14: CLABCONF0: =SB-COMEXmini; Group: NPOP
C155 = 100nF,_10V,_X7R,_10%,_0402: CLABCONF0: =SB-COMEXmini; Group: NPOP
C361 = 100pF,_50V,_NPO,_5%,_0402: CLABCONF0: =SB-COMEXmini
C362 = 100pF,_50V,_NPO,_5%,_0402_1: CLABCONF0: =SB-COMEXmini
D2 D5 = Diode_Shotky,5A,30V: CLABCONF0: =SB-COMEXmini
D3 = BAT54C: CLABCONF0: =SB-COMEXmini
FB16 = Ferrite_bead_,_30_Ohm@5A_3: CLABCONF0: =SB-COMEXmini
FB17 = Ferrite_bead_,_30_Ohm@5A_1: CLABCONF0: =SB-COMEXmini
FB18 = Ferrite_bead_,_30_Ohm@5A: CLABCONF0: =SB-COMEXmini
FB19 = Ferrite_bead_,_30_Ohm@5A_2: CLABCONF0: =SB-COMEXmini
J3 = DC_Jack_,5.5_2.5,10A,20V: CLABCONF0: =SB-COMEXmini
L8 = Ind_SIL525-2R2-2.2uH_@_2.1A: CLABCONF0: =SB-COMEXmini
L9 = Inductor_,4.7uH_,3.4A: CLABCONF0: =SB-COMEXmini
L10 = Inductor_,4.7uH_,3.4A_1: CLABCONF0: =SB-COMEXmini
P14 = Conn.,_W2B,_Header,_2x1,_1.25mm: CLABCONF0: =SB-COMEXmini
Q1 Q3 = P-MOSFET,3A,20V,110mOhm@-1.8V: CLABCONF0: =SB-COMEXmini
R59 = 3.32K,1%,0402,1_16W: CLABCONF0: =SB-COMEXmini
R60 = 10.5K_1%,0402: CLABCONF0: =SB-COMEXmini
R62 = 2.37K_1%,_0402_1: CLABCONF0: =SB-COMEXmini
R63 = 40.2k_,1%: CLABCONF0: =SB-COMEXmini
R65 = 10R,_0402: CLABCONF0: =SB-COMEXmini
R66 = 1.5K_1%,_0402: CLABCONF0: =SB-COMEXmini
R68 = Res.,6.19k,1%: CLABCONF0: =SB-COMEXmini
R69 = 2.37K_1%,_0402: CLABCONF0: =SB-COMEXmini
R70 = 40.2k_,1%_1: CLABCONF0: =SB-COMEXmini
SW1 = LP_Switc_4.5x4.5mm_SMT: CLABCONF0: =SB-COMEXmini
SW2 SW4 SW6 SW7 = TactSW_4x6mm_RA_SMT: CLABCONF0: =SB-COMEXmini; Group: Always
TP6 TP8 = TP_SMT
U17 = RT8058_,Switcher_,2A: CLABCONF0: =SB-COMEXmini
U18 U19 = RT8272,Converter,3A,24V: CLABCONF0: =SB-COMEXmini
D6 = BAT54WS: CLABCONF0: =SB-COMEXmini
D7 = 1A_Schottky_Barrier_Rectifier: CLABCONF0: =SB-COMEXmini
DS4 = LED-Yellow_1206: CLABCONF0: =SB-COMEXmini
E1 = HDR_1x2_100MIL_TH_JUMPER_1: CLABCONF0: =SB-COMEXmini
E2 = HDR_1x2_100MIL_TH_JUMPER: CLABCONF0: =SB-COMEXmini
P16 = HDR_2x4_100MIL_SMT: CLABCONF0: =SB-COMEXmini
Q4 Q13 = N-MOSFET,NDS335N,100mOhm@2.5V: CLABCONF0: =SB-COMEXmini
R76 = 348R,1%,0402,1_16W: CLABCONF0: =SB-COMEXmini
R78 = 4.75K,1%,0402,1_16W: CLABCONF0: =SB-COMEXmini
RN9 = RN,4.7K,8P4R@0805: CLABCONF0: =SB-COMEXmini
RN12 = RN,22R,8P4R@0805_0: CLABCONF0: =SB-COMEXmini
SC1 = IC,SPI_FLASH,16_Mbit_3: CLABCONF0: =NOP; P/N: 190A00800S
SW3 SW5 = TACT_SW_6x6mm_SMT: CLABCONF0: =SB-COMEXmini
U22 = IC,FLASH,SPI,64MBit: CLABCONF0: 111S32302I=SB-COMEXmini

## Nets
+3V_DP: C178.2 C182.1 P18.20(DP_PWR) U30.2(Vout) U30.3(Vout)
+5V_HDMIB: D10.CATHODE F1.2
+5V_J59: C193.2 F1.1 J4.18(+5V)
+V1.5S_PCIE: C118.1 C119.1 L8.2 R59.1 ; also on sheet 5 6
+V3.3A: C136.1 C160.1 C161.2 C162.1 C163.1 C164.1 C165.1 C166.1 D7.2(ANODE) DS4.ANODE L10.2 P17.4 Q3.2(S) R68.1 R80.2 R81.2 R82.2 RN10.1(RA1) RN10.2(RB1) RN10.3(RC1) RN10.4(RD1) RN11.1(RA1) RN11.2(RB1) RN11.3(RC1) RN11.4(RD1) U24.4(CLKEN) U24.5(VDD) U25.9(VCC1) U25.17(VCC2) U25.29(VCC3) U25.41(VCC4) ; also on sheet 2 3 5
+V3.3A_SPI: C157.2 C158.2 C159.2 D7.1(CATHODE) P16.1 R78.2 RN9.5(RD2) RN9.6(RC2) RN9.7(RB2) RN9.8(RA2) SC1.8(VDD) U22.8(VCC) ; also on sheet 7
+V3.3S: C126.1 C129.1 C130.1 C144.1 C145.1 C146.1 C147.1 C148.1 C149.1 C150.1 C151.1 C152.1 C153.1 C154.1 C155.1 C180.1 C181.2 C189.2 DS5.ANODE DS6.ANODE P35.1 P35.2 P35.3 Q3.3(D) Q10.2(G1) Q10.5(G2) R86.1 R91.1 R92.2 R96.2 R97.2 R98.1 U30.6(Vin) U30.7(Vin) ; also on sheet 2 3 4 5 6
+V5A: C113.2 C115.2 C122.1 L9.2 Q1.2(S) R60.1 R64.2 U17.9(VDD) U17.10(PVDD) U17.11(PVDD) U17.12(PVDD) ; also on sheet 4
+V5S: C114.1 C116.1 C140.1 C190.2 D8.ANODE D9.ANODE D10.ANODE Q1.3(D) ; also on sheet 2 4 5 6
+V12: FB16.1 FB17.1 J3.1(CENTRAL)
+VBATA: C121.1 C135.1 C139.1 FB16.2 FB17.2 U18.2(Vin) U19.2(Vin) ; also on sheet 7
GND: BT1.2(NEG) C113.1 C114.2 C115.1 C116.2 C117.2 C118.2 C119.2 C121.2 C122.2 C123.1 C125.2 C126.2 C127.2 C128.2 C129.2 C130.2 C131.2 C134.1 C135.2 C136.2 C138.2 C139.2 C140.2 C144.2 C145.2 C146.2 C147.2 C148.2 C149.2 C150.2 C151.2 C152.2 C153.2 C154.2 C155.2 C157.1 C158.1 C159.1 C160.2 C161.1 C162.2 C163.2 C164.2 C165.2 C166.2 C178.1 C180.2 C181.1 C182.2 C189.1 C190.1 C193.1 C361.2 C362.2 D2.ANODE D5.ANODE E2.1 FB18.2 FB19.2 J4.2(D2_Shield) J4.5(D1_Shield) J4.8(D0_Shield) J4.11(CK_Shield) J4.17(GND) J4.20(SHELL1) J4.21(SHELL2) L11.5 L11.6 L12.5 L12.6 L13.5 L13.6 L14.5 L14.6 L15.5 L15.6 L16.5 L16.6 L17.5 L17.6 L18.5 L18.6 P14.1 P14.M1 P14.M2 P16.2 P17.2 P17.10 P18.2(GND0) P18.5(GND1) P18.8(GND2) P18.11(GND3) P18.14(CNFG2) P18.16(GND6) P18.19(PWR_RTN) P18.SH1 P18.SH2 P18.SH3 P18.SH4 P35.4 P35.5 P35.6 P35.9 P35.12 P35.15 P35.18 P35.21 P35.24 P35.27 P35.30 P35.32 Q2.1(S1) Q2.4(S2) Q4.2(S) Q5.2(S) Q6.2(S) Q7.2(S) Q8.2(S) Q11.1(S1) Q11.4(S2) Q13.2(S) R61.1 R62.2 R63.2 R69.2 R70.2 R77.1 R83.1 R84.2 R85.2 R90.2 R93.1 SC1.4(VSS) SW1.1 SW1.3 SW2.1 SW2.4 SW3.1 SW3.3 SW4.1 SW4.4 SW5.1 SW5.3 SW6.1 SW6.4 SW7.1 SW7.4 TP8.1 U17.1(PGND) U17.2(PGND) U17.3(PGND) U17.5(GND) U17.17(PAD) U18.4(GND) U18.9(PAD) U19.4(GND) U19.9(PAD) U22.4(GND) U24.2(GND) U25.4(GND1) U25.16(GND2) U25.24(GND3) U25.36(GND4) U30.4(GND) ; also on sheet 2 3 4 5 6 7
GND_IN: FB18.1 FB19.1 J3.2(R) J3.SH1 J3.SH2 J3.SH3 J3.SH4
V3.3_BOOT: C132.1 U19.1(BOOT)
V3.3_FB: R68.2 R69.1 U19.5(FB)
V3.3_SS: C134.2 U19.8(SS)
V3.3_SW: C132.2 D5.CATHODE L10.1 U19.3(SW)
V3_C1: C137.2 R70.1
V3_COMP: C137.1 C138.1 U19.6(COMP)
V5W_BOOT: C120.1 U18.1(BOOT)
V5W_C1: C124.2 R63.1
V5W_COMP: C124.1 C125.1 U18.6(COMP)
V5W_FB: R60.2 R62.1 U18.5(FB)
V5W_SS: C123.2 U18.8(SS)
V5W_SW: C120.2 D2.CATHODE L9.1 U18.3(SW)
7SEG_LED_CT1: CR7B1.3(CT) CR7B1.8(COM) Q5.3(D)
7SEG_LED_CT2: CR7B2.3(CT) CR7B2.8(COM) Q6.3(D)
7SEG_LED_CT3: CR7B3.3(CT) CR7B3.8(COM) Q7.3(D)
7SEG_LED_CT4: CR7B4.3(CT) CR7B4.8(COM) Q8.3(D)
32XTAL_IN: U24.3(OSCIN) Y1.1
32XTAL_OUT: U24.1(OSCOUT) Y1.2
+VRTC: C128.1 D3.3(CATHODE) R65.2 R66.1 ; also on sheet 7
ATP_LED: Q13.3(D) R76.2 RN9.1(RA1)
BAT: BT1.1(POS) R66.2
BIOS_DIS1#: D6.ANODE E1.1 Q4.1(G) SW2.2 SW2.3 SW3.2 SW3.4 ; also on sheet 7
BUF_PLT_RST#: U25.39(GCLR#) ; also on sheet 2 3 5 7
D3_CAT: D8.CATHODE R94.2
D4_CAT: D9.CATHODE R95.2
DDI0_CLK: J4.15(DDC_CLK) Q10.6(D1) R94.1
DDI0_CLK_AUXP_IN: Q10.1(S1) R96.1 ; also on sheet 7
DDI0_DAT: J4.16(DDC_DATA) Q10.3(D2) R95.1
DDI0_DAT_AUXM_IN: Q10.4(S2) R97.1 ; also on sheet 7
DDI0_DDC_AUX_SEL: R98.2 ; also on sheet 7
DDI0_HDMI_TERM: Q2.3(D2) R99.2 R100.2 R101.2 R102.2 R103.2 R104.2 R105.2 R106.2
DDI0_LANE0_N: C184.2 ; also on sheet 7
DDI0_LANE0_P: C183.2 ; also on sheet 7
DDI0_LANE1_N: C186.2 ; also on sheet 7
DDI0_LANE1_P: C185.2 ; also on sheet 7
DDI0_LANE2_N: C188.2 ; also on sheet 7
DDI0_LANE2_P: C187.2 ; also on sheet 7
DDI0_LANE3_N: C192.2 ; also on sheet 7
DDI0_LANE3_P: C191.2 ; also on sheet 7
DDIO_HPDET_IN: J4.19(HP_DET) ; also on sheet 7
DP_AUX_N: C179.1 P18.17(AUX_CHn) R91.2
DP_AUX_P: C177.1 P18.15(AUX_CHp) R90.1
DP_EXT_PWR_EN: R92.1 U30.5(EN)
DP_REXT: R93.2 U30.8(IP)
DP_TX0_N: C169.1 L11.3
DP_TX0_P: C168.1 L11.4
DP_TX1_N: C171.1 L12.3
DP_TX1_P: C170.1 L12.4
DP_TX2_N: C173.1 L13.3
DP_TX2_P: C172.1 L13.4
DP_TX3_N: C176.1 L14.3
DP_TX3_P: C175.1 L14.4
DP_TXN0: L11.2 P18.3(ML_Lane_0n)
DP_TXN1: L12.2 P18.6(ML_Lane_1n)
DP_TXN2: L13.2 P18.9(ML_Lane_2N)
DP_TXN3: L14.2 P18.12(ML_Lane_3n)
DP_TXP0: L11.1 P18.1(ML_Lane_0p)
DP_TXP1: L12.1 P18.4(ML_Lane_1p)
DP_TXP2: L13.1 P18.7(ML_Lane_2p)
DP_TXP3: L14.1 P18.10(ML_Lane_3p)
DS5_C: DS5.CATHODE R14.1
DS6_C: DS6.CATHODE R16.1
eDP_AUXN_I2C_DAT: C179.2 R112.1 ; also on sheet 7
eDP_AUXP_I2C_CK: C177.2 R113.1 ; also on sheet 7
eDP_HPD_IN: E3.1 P18.18(Hot_Plug) ; also on sheet 7
eDP_LVDS_BKCTL: P35.31 ; also on sheet 7
eDP_LVDS_BKEN: P35.23 Q11.5(G2) ; also on sheet 7
eDP_LVDS_VDDEN: P35.22 Q11.2(G1) ; also on sheet 7
eDP_N0_A2-: C169.2 R67.1 ; also on sheet 7
eDP_N1_A1-: C171.2 R44.1 ; also on sheet 7
eDP_N2_A0-: C173.2 R29.1 ; also on sheet 7
eDP_N3_CK-: C176.2 R111.1 ; also on sheet 7
eDP_P0_A2+: C168.2 R58.1 ; also on sheet 7
eDP_P1_A1+: C170.2 R43.1 ; also on sheet 7
eDP_P2_A0+: C172.2 R28.1 ; also on sheet 7
eDP_P3_CK+: C175.2 R110.1 ; also on sheet 7
EN_3.3S: C117.1 C127.1 Q1.1(G) Q2.6(D1) Q3.1(G) R64.1
EXT_CLED: DS4.CATHODE R76.1
EXT_DELAY: E1.2 R77.2
EXT_RTC: D3.2(ANODE2) P14.2
FB1.5S_PCIE: R59.2 R61.2 U17.4(FB)
HDMIB_TX0+: J4.7(D0+) L17.1 R103.1
HDMIB_TX0-: J4.9(D0-) L17.2 R104.1
HDMIB_TX1+: J4.4(D1+) L16.1 R101.1
HDMIB_TX1-: J4.6(D1-) L16.2 R102.1
HDMIB_TX2+: J4.1(D2+) L15.1 R99.1
HDMIB_TX2-: J4.3(D2-) L15.2 R100.1
HDMIB_TXC+: J4.10(CK+) L18.1 R105.1
HDMIB_TXC-: J4.12(CK-) L18.2 R106.1
HDMIB_TXN0: C188.1 L17.3
HDMIB_TXN1: C186.1 L16.3
HDMIB_TXN2: C184.1 L15.3
HDMIB_TXNC: C192.1 L18.3
HDMIB_TXP0: C187.1 L17.4
HDMIB_TXP1: C185.1 L16.4
HDMIB_TXP2: C183.1 L15.4
HDMIB_TXPC: C191.1 L18.4
LED_BKEN: Q11.3(D2) R16.2
LED_MUX_HI80: Q5.1(G) U25.28(IO23)
LED_MUX_HI81: Q7.1(G) U25.31(IO25)
LED_MUX_LO80: Q6.1(G) U25.27(IO22)
LED_MUX_LO81: Q8.1(G) U25.30(IO24)
LED_SEGA: CR7B1.7(A) CR7B2.7(A) CR7B3.7(A) CR7B4.7(A) RN10.7(RB2) U25.21(IO17)
LED_SEGB: CR7B1.6(B) CR7B2.6(B) CR7B3.6(B) CR7B4.6(B) RN10.6(RC2) U25.20(IO16)
LED_SEGC: CR7B1.4(C) CR7B2.4(C) CR7B3.4(C) CR7B4.4(C) RN10.5(RD2) U25.19(IO15)
LED_SEGD: CR7B1.2(D) CR7B2.2(D) CR7B3.2(D) CR7B4.2(D) RN11.8(RA2) U25.18(IO14)
LED_SEGDP: CR7B1.5(DP) CR7B2.5(DP) CR7B3.5(DP) CR7B4.5(DP) RN10.8(RA2) U25.12(IO10)
LED_SEGE: CR7B1.1(E) CR7B2.1(E) CR7B3.1(E) CR7B4.1(E) RN11.7(RB2) U25.15(IO13)
LED_SEGF: CR7B1.9(F) CR7B2.9(F) CR7B3.9(F) CR7B4.9(F) RN11.6(RC2) U25.14(IO12)
LED_SEGG: CR7B1.10(G) CR7B2.10(G) CR7B3.10(G) CR7B4.10(G) RN11.5(RD2) U25.13(IO11)
LED_VDDEN: Q11.6(D1) R14.2
LPC_AD0: U25.2(IO2) ; also on sheet 2 7
LPC_AD1: U25.3(IO3) ; also on sheet 2 7
LPC_AD2: U25.5(IO4) ; also on sheet 2 7
LPC_AD3: U25.6(IO5) ; also on sheet 2 7
LPC_CLK: U25.37(GCLK1) ; also on sheet 2 7
LPC_FRAME#: U25.44(IO32) ; also on sheet 2 7
LVDS_A3+: P35.16 ; also on sheet 7
LVDS_A3-: P35.17 ; also on sheet 7
LVDS_A_CLKM: P35.20 R111.2
LVDS_A_CLKP: P35.19 R110.2
LVDS_A_DATAN0: P35.8 R29.2
LVDS_A_DATAN1: P35.11 R44.2
LVDS_A_DATAN2: P35.14 R67.2
LVDS_A_DATAP0: P35.7 R28.2
LVDS_A_DATAP1: P35.10 R43.2
LVDS_A_DATAP2: P35.13 R58.2
LVDS_DDCCLK: P35.28 R113.2
LVDS_DDCDATA: P35.29 R112.2
LVDS_EN_HPD: E3.2 R86.2
LX1.5_PCIE: L8.1 U17.13(LX) U17.14(LX) U17.15(LX)
OE#_PORT80: R85.1 U25.38(OE1)
PLD_PD: R84.1 U25.42(IO30)
PWRBTN#: C361.1 SW6.2 SW6.3 ; also on sheet 7
RTC_RST#_SW: C131.1 R65.1 SW1.2 SW1.4 TP6.1
SLP_S3#: Q2.2(G1) Q2.5(G2) U17.7(EN) ; also on sheet 7
SPI0_HOLD#: Q4.3(D) Q13.1(G) RN9.4(RD1) SC1.7(HOLD#) U22.7(HOLD#)
SPI0_WP#: RN9.2(RB1) SC1.3(WP#) U22.3(WP#)
SPI_B_CLK: P16.4 RN12.8(RA2) ; also on sheet 7
SPI_B_CS0#: P16.3 R78.1 RN12.5(RD2) ; also on sheet 7
SPI_B_MISO: P16.5 RN12.7(RB2) ; also on sheet 7
SPI_B_MOSI: P16.6 RN12.6(RC2) ; also on sheet 7
SPI_NOR_CLK: RN12.1(RA1) SC1.6(SCK) U22.6(SCK)
SPI_NOR_CS0#: RN9.3(RC1) RN12.4(RD1) SC1.1(CE#) U22.1(CS#)
SPI_NOR_MISO: RN12.2(RB1) SC1.2(SO) U22.2(DO)
SPI_NOR_MOSI: RN12.3(RC1) SC1.5(SI) U22.5(DI)
SUS_CLK: U24.6(CLKOUT) U25.40(OE2/GCLK2)
SYS_RST#_IN: C362.1 SW7.2 SW7.3 ; also on sheet 7
TCK_P80: P17.1 R83.2 U25.26(TCK/IO21)
TDI_P80: P17.9 R80.1 U25.1(TDI/IO1)
TDO_P80: P17.3 R82.1 U25.32(TDO/IO26)
TEST1#: D6.CATHODE E2.2 SW4.2 SW4.3 SW5.2 SW5.4 ; also on sheet 7
TMS_P80: P17.5 R81.1 U25.7(TMS/IO6)

Not connected (* = marked no-connect by the designer): D3 1(ANODE1); J4 13(CE_Remote)* 14(NC)*; P16 7* 8*; P17 6* 7* 8*; P18 13(CNFG1); P35 25* 26* 33* 34* 35* 36* 37* 38* 39* 40*; U17 6(NC) 8(NC) 16(NC); U18 7(EN); U19 7(EN); U25 8(IO7)* 10(IO8)* 11(IO9)* 22(IO18)* 23(IO19)* 25(IO20)* 33(IO27)* 34(IO28)* 35(IO29)* 43(IO31)*; U30 1(FLG)*

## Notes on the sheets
sheet 8
- +V1.5S POWER SOURCE MAX 2A
- +V5A POWER SOURCE MAX 3A
- VBATA min 9V
- Vout=0.6(1+R1/R2)
- NP
- RTC Circuitry
- +V3.3A POWER SOURCE MAX 3A
- NP
sheet 9
- EC/BIOS SPI
- 8 PIN  SPI DEVICES
- SPI PROGRAMMING HEADER
- SPI BIOS EXT
- DEBUG (DON'T COPY THIS PAGE)
sheet 10
- DEBUG (DON'T COPY THIS PAGE)
- PORT 80 DISPLAY
- LPC & MISC
sheet 11
- DDI0 - HDMI
- DDI0
sheet 12
- PORT DDI1 - DP
- NP
- According with Intel's errata
- LVDS OPTIONS
- eDP/LVDS
